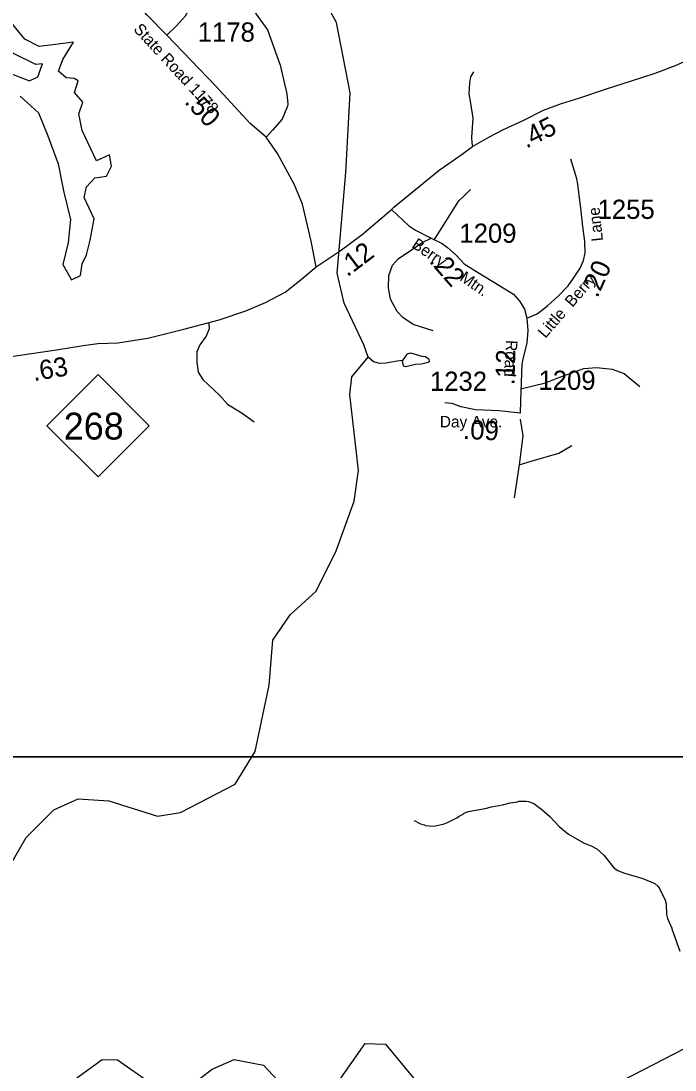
# Model space of a CAD drawing. Extents: x 1248089 to 1457196, y 820910 to 988753.
# Drawn here: x 1341854 to 1346110, y 866798 to 873625 of the extents above; entities that cross this region are included whole.
import ezdxf

# ---------------------------------------------------------------- set-up
doc = ezdxf.new("R2010")
doc.units = 0
for name, color, linetype in [('Exist Hydrographic Buffer Line', 7, 'Continuous'), ('Exist Hydrographic Misc Water Feature', 7, 'Continuous'), ('Exist Hydrographic Reservoir', 7, 'Continuous'), ('Exist Road Non-System Type 51', 7, 'Continuous'), ('Exist Road Primary NC Attributed', 7, 'Continuous'), ('Exist Road Primary NC Shield CELL', 7, 'Continuous'), ('Exist Road Primary NC Shield Number Label', 7, 'Continuous'), ('Exist Road Secondary Type 51 Attributed', 7, 'Continuous'), ('Exist Road Secondary Type 51 Label', 7, 'Continuous'), ('Map Preparation Inset Cut Line', 7, 'Continuous'), ('Prop CMT Slope Fill', 7, 'Continuous'), ('Prop GRAU CAT1 Cell', 7, 'Continuous'), ('Prop Lane Lines', 7, 'Continuous')]:
    doc.layers.add(name, color=color, linetype=linetype)

msp = doc.modelspace()

# ---------------------------------------------------------------- linework, layer by layer
at = {"layer": 'Exist Hydrographic Buffer Line'}
msp.add_lwpolyline([(1341452.9, 873625.9), (1341530.6, 873460.7), (1341483.6, 873263.5), (1341476.3, 873219.4), (1341541.4, 873288.6), (1341661.7, 873331.6), (1341910.1, 873235.2), (1341964.9, 873261.2), (1341994.8, 873346.7), (1341950.9, 873342), (1341806.6, 873414.2), (1341640.6, 873615.3), (1341493.7, 873840.3)], dxfattribs=at)
at = {"layer": 'Exist Hydrographic Misc Water Feature'}
for points in [[(1343958, 871788.2), (1343912, 871982.8), (1343967.9, 872638.2), (1343997, 873156.3), (1343906.9, 873614.5), (1343851, 873717.3), (1343735, 873762.3), (1343646, 873888.9), (1343630.9, 873964.7), (1343396, 874301), (1343396, 874652.2), (1343216.9, 874839.6), (1343143.9, 874949.4), (1343210.2, 875427.2), (1343283.8, 875504.1), (1343632.9, 875831), (1343725.8, 875933.5), (1343732.2, 875955.9)], [(1341706, 867999), (1341888, 868310.6), (1342068, 868490.8), (1342227.1, 868563), (1342427, 868549.2), (1342742, 868450.9), (1342893.1, 868474.2), (1343247, 868657.5), (1343377, 868871.6), (1343470, 869303), (1343493, 869594.7), (1343605, 869759.9), (1343775, 869914), (1343906, 870177.4), (1344021.1, 870500), (1344051, 870699.6), (1343995, 871193.2), (1344006, 871307.9), (1344112.4, 871436.4), (1344085, 871516.4), (1343958, 871788.2)], [(1345697.3, 866692), (1346372.2, 867041.6), (1346638.1, 867023.5), (1346798.1, 867069.5), (1347026.1, 867238.9), (1347321.2, 867374.1), (1347417.1, 867572.5), (1347434.1, 867966), (1347389.1, 868173.8), (1347501.1, 868722.9), (1347595.1, 868845.9), (1347635.1, 869111), (1347774.1, 869367.5), (1347919.1, 869505.7), (1347922.1, 869679.7), (1347581.1, 870064.1), (1347540.2, 870190.4), (1347479.3, 870799.1), (1347391.1, 870934.5), (1347132.1, 871281.2), (1347060, 871423.8), (1347322.2, 871702.5)], [(1344334.9, 871414.7), (1344301.2, 871411.9), (1344228.8, 871397.6), (1344188.8, 871396.6), (1344149, 871407.5), (1344112.4, 871436.4)], [(1344334.9, 871414.7), (1344343.4, 871420.9), (1344368.2, 871458.3), (1344388.4, 871465.8), (1344461.9, 871444.1), (1344485.9, 871441.5), (1344501.6, 871431.1), (1344507.4, 871423), (1344509.2, 871411), (1344503, 871403.1), (1344460.8, 871392.1), (1344420.7, 871389), (1344356.3, 871374.6), (1344348.4, 871376.7), (1344342.5, 871382.9), (1344334.9, 871414.7)], [(1344413.4, 868421.6), (1344453, 868400.6), (1344478.8, 868394), (1344484.8, 868389.9), (1344536.7, 868384.6), (1344560.8, 868388.1), (1344600.9, 868397.1), (1344625.1, 868406.5), (1344689.9, 868439), (1344706.1, 868450.6), (1344730.4, 868462), (1344738.6, 868469.8), (1344762.8, 868479.2), (1344875.3, 868500.6), (1344915.6, 868511.6), (1344987.9, 868523.9), (1345036.2, 868536.8), (1345084.4, 868543.6), (1345092.5, 868547.4), (1345140.5, 868548.2), (1345156.4, 868545.9), (1345190.2, 868533.1), (1345243.3, 868493.8), (1345294.2, 868448.6), (1345356.8, 868383.2), (1345415.7, 868333.7), (1345518.3, 868273.3), (1345564, 868256.2), (1345601.6, 868237.3), (1345646.6, 868196.3), (1345714.7, 868110.7), (1345738.4, 868096.1), (1345774, 868081.2), (1345899.2, 868044.2), (1345978.6, 868012.3), (1346000.1, 867991.8), (1346011.7, 867975.6), (1346046.2, 867902.7), (1346051.6, 867878.6), (1346054, 867810.6), (1346061.4, 867784.4), (1346088, 867721.8), (1346087.9, 867715.8), (1346140.6, 867570.5)], [(1343921.1, 866723.5), (1344094.1, 866969.5), (1344227, 866966.9), (1344462.1, 866679.8)], [(1342060, 866632.8), (1342382.1, 866866), (1342482, 866864), (1342802, 866640.8)], [(1342937, 866680.8), (1343098, 866802.4), (1343241, 866865.2), (1343432, 866828.5), (1343586, 866664.5)]]:
    msp.add_lwpolyline(points, dxfattribs=at)
at = {"layer": 'Exist Hydrographic Reservoir'}
msp.add_lwpolyline([(1341848.8, 873135.8), (1341968.3, 873027.8), (1342030, 872877.4), (1342095.5, 872696.2), (1342130.2, 872518.8), (1342176.4, 872333.7), (1342161, 872183.3), (1342126.3, 872040.6), (1342184.1, 871940.4), (1342241.9, 871967.4), (1342253.5, 872044.5), (1342280.4, 872102.3), (1342303.6, 872198.7), (1342330.5, 872337.6), (1342265, 872476.4), (1342280.4, 872545.8), (1342334.4, 872603.6), (1342411.5, 872615.2), (1342442.3, 872680.8), (1342430.7, 872754), (1342345.9, 872715.5), (1342253.5, 872912.1), (1342230.3, 873020.1), (1342257.3, 873097.3), (1342203.4, 873159), (1342226.5, 873236.1), (1342199.5, 873251.5), (1342149.4, 873255.4), (1342099.3, 873297.8), (1342126.3, 873374.9), (1342195.7, 873486.7), (1342080.1, 873471.3), (1341972.2, 873459.7), (1341879.7, 873506), (1341733.2, 873683.4)], dxfattribs=at)
at = {"layer": 'Exist Road Non-System Type 51'}
for p, q in [((1345470.4, 872597.8), (1345431.5, 872724.6)), ((1345095, 870737), (1345063.7, 870521.8))]:
    msp.add_line(p, q, dxfattribs=at)
for points in [[(1342804.4, 873531.8), (1342866.6, 873592.2), (1342924.4, 873657.6), (1343100.5, 873969.7)], [(1343100.5, 873969.7), (1343339.5, 873733.1), (1343457.7, 873567), (1343540.7, 873338), (1343583.4, 873151.7), (1343591, 873083.7), (1343588.5, 873071.2), (1343553.1, 872986.5), (1343490.2, 872913.5), (1343448.7, 872868.8)], [(1344800.9, 873293.7), (1344796.3, 873289), (1344779.5, 873260.5), (1344772.6, 873222.5), (1344768.4, 873150.5), (1344779.5, 873089.5), (1344794.9, 872991.8), (1344789.3, 872929.3), (1344785.1, 872865.6), (1344787.9, 872831.6), (1344792.1, 872807.2)], [(1344545.4, 872202.8), (1344702.6, 872455.4), (1344742.9, 872491.9), (1344779.4, 872528.5)], [(1344535.5, 871607.5), (1344406.6, 871649.7), (1344338.7, 871694.2), (1344301.2, 871734.1), (1344259, 871813.8), (1344245, 871888.8), (1344247.3, 871968.5), (1344270.7, 872036.5), (1344308.2, 872076.3), (1344394.9, 872134.9), (1344465.2, 872184.2), (1344523.2, 872211.2)], [(1343076, 871657.9), (1343078.4, 871620.4), (1343059.6, 871573.5), (1343017.4, 871517.2), (1342998.7, 871472.7), (1342998.7, 871404.7), (1343008.1, 871339.1), (1343038.5, 871292.2), (1343148.6, 871186.7), (1343197.8, 871130.4), (1343293.9, 871071.8), (1343371.2, 871015.6)], [(1345106.7, 871229.9), (1345267, 871269), (1345353, 871304.2), (1345517.2, 871362.9), (1345599.3, 871370.7), (1345700.9, 871359), (1345779.1, 871331.6), (1345880.7, 871245.5)], [(1345102.8, 871034.3), (1345118.5, 870924.8), (1345095, 870737)], [(1345095, 870737), (1345173.2, 870760.5), (1345353, 870811.3), (1345439, 870862.2)]]:
    msp.add_lwpolyline(points, dxfattribs=at)
at = {"layer": 'Exist Road Primary NC Attributed'}
for points in [[(1344264.2, 872398.1), (1344280.5, 872412.8), (1344576.1, 872654.6), (1344674, 872722.4), (1344725.7, 872757.7), (1344792.1, 872807.2), (1344899.1, 872869), (1344992.8, 872919.2), (1345125.7, 872980.2), (1345254.3, 873044), (1345371.1, 873088.1), (1345483, 873123.4), (1345663.4, 873183.1), (1345820.7, 873234), (1345980.2, 873285.6), (1346113, 873335.8), (1346223.5, 873384.6), (1346348.7, 873442.3)], [(1343775.9, 872024.4), (1343932.1, 872127.9), (1344074, 872235.2), (1344247.8, 872383.4), (1344264.2, 872398.1)], [(1340587.3, 871274.3), (1340760.4, 871309), (1340965, 871335.3), (1341263.2, 871367.5), (1341447.3, 871390.9), (1342084.5, 871484.5), (1342259.9, 871513.8), (1342355.2, 871525.3), (1342483.8, 871531.1), (1342679.6, 871560.4), (1342913.5, 871618.9), (1343144.4, 871680.3), (1343316.8, 871738.8), (1343444.4, 871793.6), (1343573.1, 871860.9), (1343666.6, 871934), (1343775.9, 872024.4)]]:
    msp.add_lwpolyline(points, dxfattribs=at)
at = {"layer": 'Exist Road Primary NC Shield CELL'}
msp.add_lwpolyline([(1342023.4, 870990.5), (1342356.4, 871323.5), (1342689.4, 870990.5), (1342356.4, 870657.5)], close=True, dxfattribs=at)
at = {"layer": 'Exist Road Secondary Type 51 Attributed'}
for points in [[(1343775.9, 872024.4), (1343741.9, 872191.8), (1343686, 872431.9), (1343632.4, 872562.4), (1343523, 872762.8), (1343448.7, 872868.8), (1343346.3, 872957.4), (1343120.4, 873202.1), (1342804.4, 873531.8), (1342674, 873664.7), (1342566.9, 873790.5), (1342527.3, 873867.4), (1342515.6, 873942), (1342518, 874007.3), (1342550.6, 874112.1), (1342581.3, 874209.5)], [(1345145.3, 871690.9), (1345212.4, 871719.1), (1345282.4, 871774.1), (1345349.9, 871834.1), (1345414.9, 871901.7), (1345449.9, 871951.7), (1345492.4, 872016.7), (1345514.9, 872066.8), (1345524.9, 872114.3), (1345522.4, 872189.3), (1345509.9, 872286.9), (1345499.9, 872387), (1345477.4, 872562.1), (1345470.4, 872597.8)], [(1344264.2, 872398.1), (1344376.5, 872293), (1344421.1, 872263.3), (1344523.2, 872211.2), (1344593.8, 872175.9), (1344629.1, 872149.9), (1344686.6, 872101.6), (1344736.8, 872044), (1344835.2, 871982.6), (1345002.3, 871882.3), (1345058, 871847), (1345098.9, 871798.7), (1345130.4, 871750.3), (1345145.3, 871690.9)], [(1345145.3, 871690.9), (1345152.8, 871610.3), (1345145.7, 871529.4), (1345122, 871431.9), (1345112.5, 871391.5), (1345105.3, 871153.8), (1345103, 871072.9)], [(1345103, 871072.9), (1344965.2, 871087.2), (1344810.7, 871094.3), (1344715.7, 871113.4), (1344658.7, 871134.7), (1344611.2, 871139.5)]]:
    msp.add_lwpolyline(points, dxfattribs=at)
at = {"layer": 'Map Preparation Inset Cut Line'}
for points in [[(1313026.2, 913085.2), (1388709.5, 913085.2), (1388709.5, 884379.9), (1373500.6, 884376.6), (1373500.6, 868836.7), (1313026.2, 868836.7)], [(1313026.2, 824588.2), (1313026.2, 868836.7), (1388709.5, 868836.7), (1388709.5, 835631.5), (1373500.6, 835631.5), (1373500.6, 824588.2)]]:
    msp.add_lwpolyline(points, close=True, dxfattribs=at)

# ---------------------------------------------------------------- texts
at = {"layer": 'Exist Road Primary NC Shield Number Label'}
msp.add_text('268', height=175, dxfattribs=at).set_placement((1342132.6, 870900.8))
at = {"layer": 'Exist Road Secondary Type 51 Label'}
for s, rotation, p in [('State Road 1178', 312.63778, (1342582.2, 873567.5)), (' Lane', 96.07267, (1345644.2, 872166.6)), ('Berry     Mtn.', 325.3153, (1344391.8, 872155.3)), ('Little  Berry', 48.92836, (1345266, 871555.8)), ('Road', 266.63688, (1345010.7, 871549.7))]:
    msp.add_text(s, height=75, rotation=rotation, dxfattribs=at).set_placement(p)
msp.add_text('Day Ave.', height=75, dxfattribs=at).set_placement((1344579.4, 870979.8))
at = {"layer": 'Prop CMT Slope Fill'}
for s, rotation, p in [('.45', 26.36821, (1345141.5, 872793.6)), ('.12', 37.11028, (1343977.3, 871956.1)), ('.63', 9.46954, (1341938.4, 871280.8))]:
    msp.add_text(s, height=125, rotation=rotation, dxfattribs=at).set_placement(p)
at = {"layer": 'Prop GRAU CAT1 Cell'}
for s, rotation, p in [('.50', 312.70913, (1342913, 873094.5)), ('.22', 311.03206, (1344505.7, 872060.2)), ('.20', 65.78917, (1345604.2, 871817.7)), ('.12', 88.2831, (1345064.7, 871253)), ('.09', 357.35518, (1344728.5, 870905.5))]:
    msp.add_text(s, height=125, rotation=rotation, dxfattribs=at).set_placement(p)
at = {"layer": 'Prop Lane Lines'}
for s, p in [('1178', (1343004.3, 873490.4)), ('1255', (1345605.6, 872336.7)), ('1209', (1344706.5, 872181.2)), ('1232', (1344514.8, 871217.7)), ('1209', (1345221.1, 871224.2))]:
    msp.add_text(s, height=125, dxfattribs=at).set_placement(p)

doc.saveas('drawing.dxf')
